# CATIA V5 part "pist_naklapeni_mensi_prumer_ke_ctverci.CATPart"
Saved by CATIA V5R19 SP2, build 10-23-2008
Part number: pist_naklapeni_ke_ctverci
Bounding box of the stored display mesh (mm): x -55 to 55, y -55 to 55, z 0 to 524.812
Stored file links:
  C:\Users\Martiin\Desktop\9.semestr\Projekt-diplomka\3D model\pist_naklapeni_mensi_prumer_ke_ctverci.CATPart
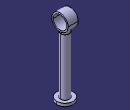
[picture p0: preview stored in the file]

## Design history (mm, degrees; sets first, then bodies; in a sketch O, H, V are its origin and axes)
Body1 (main body)
  Sketch1 on xy-plane, origin (0, 0, 0), H (1, 0, 0), V (0, 1, 0)
    circle A1 centre (0, 0) radius 30
    radius A1 = 30
  Pad1: profile Sketch1, direction (0, 0, 1), length 400
  Sketch2 on yz-plane, origin (0, 0, 0), H (0, 1, 0), V (0, 0, 1)
    circle A1 centre (0, 470) radius 45
    point P1 (0, 470)
    circle A2 centre (0, 470) radius 55
    reference projected line E1 (-35, 400) -> (35, 400) from edge [face of Pad1 from Sketch1.A1 | end face of Pad1]
    distance P1 E1 = 70
    radius A2 = 55
    radius A1 = 45
    coincidence: P1 V
    concentricity: A2 A1
  Pad2: profile Sketch2, direction (1, 0, 0), length 34, mirrored extent
  Sketch3 on end face of Pad1, origin (0, 0, 400), H (1, 0, 0), V (0, 1, 0)
    circle A1 centre (0, 0) radius 27.5
    radius A1 = 27.5
  Pad3: profile Sketch3, direction (0, 0, 1), up to the existing solid (limit type 2)
  Sketch4 on start face of Pad1, origin (0, 0, 0), H (1, 0, 0), V (0, -1, 0)
    circle A1 centre (0, 0) radius 55
    radius A1 = 55
  Pad4: profile Sketch4, direction (0, 0, 1), length 20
